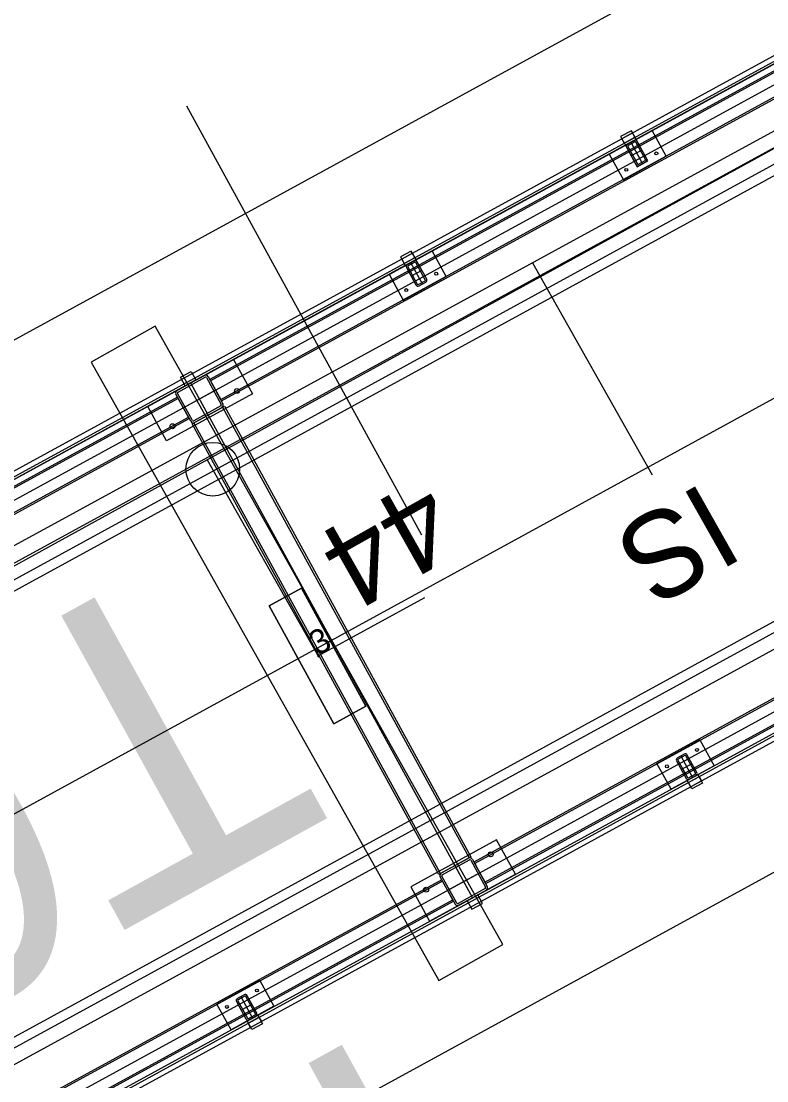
# Model space of a CAD drawing. Extents: x -783978 to -783565, y -1064821 to -1064596.
# Drawn here: x -783779.173 to -783776.126, y -1064690.963 to -1064686.63 of the extents above; entities that cross this region are included whole.
import ezdxf

# ---------------------------------------------------------------- set-up
doc = ezdxf.new("R2010")
doc.units = 0
for name, color, linetype in [('Default', 7, 'Continuous'), ('SO 01_20_01', 7, 'Continuous'), ('SO 01_50_01', 7, 'Continuous'), ('SO 01_74_01', 7, 'Continuous'), ('SO 01_77_01', 7, 'Continuous'), ('SO 01_86_04', 7, 'Continuous')]:
    doc.layers.add(name, color=color, linetype=linetype)

# ---------------------------------------------------------------- blocks, each defined once
blk = doc.blocks.new('POINT_DISPLAY')
at = {"layer": 'Default'}
blk.add_line((0, 0), (0, 0), dxfattribs=at)

msp = doc.modelspace()

# ---------------------------------------------------------------- linework, layer by layer
at = {"layer": 'SO 01_20_01'}
for p, q in [((-783735.0054, -1064663.7532), (-783787.4671, -1064692.4555)), ((-783735.2041, -1064664.4318), (-783786.7885, -1064692.6541)), ((-783786.6445, -1064692.9173), (-783735.3233, -1064664.839)), ((-783738.0171, -1064666.3812), (-783786.4402, -1064692.874)), ((-783786.421, -1064692.9091), (-783737.9979, -1064666.4163)), ((-783737.8741, -1064667.2605), (-783785.3352, -1064693.2269)), ((-783785.6531, -1064694.3127), (-783737.23, -1064667.82)), ((-783737.0912, -1064667.858), (-783785.7805, -1064694.4964)), ((-783737.2108, -1064667.855), (-783785.6339, -1064694.3478)), ((-783785.6366, -1064694.7596), (-783736.9472, -1064668.1212)), ((-783746.2961, -1064673.8055), (-783785.8354, -1064695.4379))]:
    msp.add_line(p, q, dxfattribs=at)
at = {"layer": 'SO 01_50_01'}
for p, q in [((-783786.7885, -1064692.6541), (-783725.4827, -1064659.1131)), ((-783778.0156, -1064687.8544), (-783773.6292, -1064685.4546)), ((-783778.0156, -1064687.8545), (-783773.6292, -1064685.4547)), ((-783778.0156, -1064687.8545), (-783773.6292, -1064685.4547)), ((-783777.5357, -1064688.7317), (-783778.4956, -1064686.9771)), ((-783782.4021, -1064690.2543), (-783778.0156, -1064687.8544)), ((-783782.402, -1064690.2544), (-783778.0156, -1064687.8545)), ((-783782.402, -1064690.2544), (-783778.0156, -1064687.8545))]:
    msp.add_line(p, q, dxfattribs=at)
at = {"layer": 'SO 01_74_01'}
for p, q in [((-783735.2185, -1064664.4055), (-783786.6099, -1064692.5222)), ((-783786.6003, -1064692.5398), (-783735.2089, -1064664.423)), ((-783785.4388, -1064694.6628), (-783745.8293, -1064672.9921)), ((-783745.8197, -1064673.0096), (-783785.4292, -1064694.6803)), ((-783775.8367, -1064686.6908), (-783778.4028, -1064688.0947)), ((-783775.8337, -1064686.6964), (-783778.3998, -1064688.1003)), ((-783778.3578, -1064688.1769), (-783775.7918, -1064686.773)), ((-783778.3548, -1064688.1825), (-783775.7888, -1064686.7786)), ((-783776.6794, -1064687.0778), (-783776.7233, -1064687.1018)), ((-783776.7233, -1064687.1018), (-783776.7041, -1064687.1369)), ((-783776.6746, -1064687.0866), (-783776.7185, -1064687.1106)), ((-783776.7185, -1064687.1106), (-783776.7089, -1064687.1281)), ((-783776.7089, -1064687.1281), (-783776.665, -1064687.1041)), ((-783776.7041, -1064687.1369), (-783776.6602, -1064687.1129)), ((-783776.6602, -1064687.1129), (-783776.6794, -1064687.0778)), ((-783776.665, -1064687.1041), (-783776.6746, -1064687.0866)), ((-783777.5787, -1064687.5698), (-783777.6225, -1064687.5938)), ((-783777.6225, -1064687.5938), (-783777.6033, -1064687.6288)), ((-783777.5739, -1064687.5785), (-783777.6177, -1064687.6025)), ((-783777.6081, -1064687.6201), (-783777.5643, -1064687.5961)), ((-783777.5595, -1064687.6048), (-783777.5787, -1064687.5698)), ((-783777.5643, -1064687.5961), (-783777.5739, -1064687.5785)), ((-783777.6177, -1064687.6025), (-783777.6081, -1064687.6201)), ((-783777.6033, -1064687.6288), (-783777.5595, -1064687.6048)), ((-783778.5217, -1064688.0857), (-783778.4779, -1064688.0617)), ((-783778.4779, -1064688.0617), (-783778.4587, -1064688.0968)), ((-783778.5025, -1064688.1208), (-783778.5217, -1064688.0857)), ((-783778.4587, -1064688.0968), (-783778.5025, -1064688.1208)), ((-783778.4028, -1064688.0947), (-783778.3548, -1064688.1825)), ((-783778.3998, -1064688.1003), (-783778.3578, -1064688.1769)), ((-783778.5344, -1064688.1667), (-783781.1005, -1064689.5707)), ((-783778.5314, -1064688.1723), (-783781.0974, -1064689.5762)), ((-783778.4864, -1064688.2545), (-783778.5344, -1064688.1667)), ((-783778.4894, -1064688.2489), (-783778.5314, -1064688.1723)), ((-783778.4744, -1064688.2764), (-783778.3428, -1064688.2044)), ((-783778.4674, -1064688.2726), (-783778.3498, -1064688.2082)), ((-783778.3498, -1064688.2082), (-783777.3419, -1064690.0505)), ((-783778.3428, -1064688.2044), (-783777.3349, -1064690.0467)), ((-783781.0555, -1064689.6529), (-783778.4894, -1064688.2489)), ((-783781.0525, -1064689.6584), (-783778.4864, -1064688.2545)), ((-783777.4665, -1064690.1187), (-783778.4744, -1064688.2764)), ((-783777.4594, -1064690.1149), (-783778.4674, -1064688.2726)), ((-783774.7568, -1064688.6647), (-783777.3229, -1064690.0686)), ((-783774.7538, -1064688.6703), (-783777.3198, -1064690.0742)), ((-783777.2779, -1064690.1508), (-783774.7118, -1064688.7469)), ((-783777.2749, -1064690.1564), (-783774.7088, -1064688.7525)), ((-783776.4514, -1064689.7343), (-783776.4075, -1064689.7103)), ((-783776.4466, -1064689.7431), (-783776.4027, -1064689.7191)), ((-783776.4075, -1064689.7103), (-783776.3883, -1064689.7454)), ((-783776.4027, -1064689.7191), (-783776.3931, -1064689.7366)), ((-783776.4322, -1064689.7694), (-783776.4514, -1064689.7343)), ((-783776.437, -1064689.7606), (-783776.4466, -1064689.7431)), ((-783776.3931, -1064689.7366), (-783776.437, -1064689.7606)), ((-783776.3883, -1064689.7454), (-783776.4322, -1064689.7694)), ((-783777.3349, -1064690.0467), (-783777.4665, -1064690.1187)), ((-783777.3419, -1064690.0505), (-783777.4594, -1064690.1149)), ((-783777.3229, -1064690.0686), (-783777.2749, -1064690.1564)), ((-783777.3198, -1064690.0742), (-783777.2779, -1064690.1508)), ((-783777.4545, -1064690.1406), (-783780.0205, -1064691.5445)), ((-783777.4514, -1064690.1462), (-783780.0175, -1064691.5501)), ((-783777.4065, -1064690.2284), (-783777.4545, -1064690.1406)), ((-783777.4095, -1064690.2228), (-783777.4514, -1064690.1462)), ((-783779.9755, -1064691.6267), (-783777.4095, -1064690.2228)), ((-783779.9725, -1064691.6323), (-783777.4065, -1064690.2284)), ((-783777.3067, -1064690.2023), (-783777.3506, -1064690.2263)), ((-783777.3506, -1064690.2263), (-783777.3314, -1064690.2614)), ((-783777.3314, -1064690.2614), (-783777.2875, -1064690.2374)), ((-783777.2875, -1064690.2374), (-783777.3067, -1064690.2023)), ((-783778.2498, -1064690.7183), (-783778.206, -1064690.6943)), ((-783778.245, -1064690.727), (-783778.2012, -1064690.703)), ((-783778.206, -1064690.6943), (-783778.1868, -1064690.7294)), ((-783778.2012, -1064690.703), (-783778.1916, -1064690.7206)), ((-783778.2306, -1064690.7534), (-783778.2498, -1064690.7183)), ((-783778.2354, -1064690.7446), (-783778.245, -1064690.727)), ((-783778.1916, -1064690.7206), (-783778.2354, -1064690.7446)), ((-783778.1868, -1064690.7294), (-783778.2306, -1064690.7534))]:
    msp.add_line(p, q, dxfattribs=at)
for points in [[(-783735.1681, -1064664.4976), (-783787.4762, -1064693.1159)], [(-783734.0882, -1064666.4715), (-783786.3963, -1064695.0898)], [(-783776.6685, -1064687.1174), (-783776.6958, -1064687.1323)], [(-783776.6996, -1064687.1452), (-783776.6606, -1064687.2163)], [(-783776.694, -1064687.1421), (-783776.6551, -1064687.2133)], [(-783776.6655, -1064687.1229), (-783776.6928, -1064687.1379)], [(-783776.6822, -1064687.1249), (-783776.6342, -1064687.2126)], [(-783776.6362, -1064687.1567), (-783776.6801, -1064687.1807)], [(-783776.6223, -1064687.1953), (-783776.6612, -1064687.1242)], [(-783776.6168, -1064687.1923), (-783776.6557, -1064687.1212)], [(-783776.6508, -1064687.2145), (-783776.6236, -1064687.1996)], [(-783776.6478, -1064687.2201), (-783776.6205, -1064687.2051)], [(-783777.5988, -1064687.6371), (-783777.5599, -1064687.7083)], [(-783777.5677, -1064687.6094), (-783777.595, -1064687.6243)], [(-783777.5933, -1064687.6341), (-783777.5543, -1064687.7053)], [(-783777.5647, -1064687.6149), (-783777.592, -1064687.6298)], [(-783777.5814, -1064687.6168), (-783777.5334, -1064687.7046)], [(-783777.5215, -1064687.6873), (-783777.5604, -1064687.6162)], [(-783777.516, -1064687.6843), (-783777.5549, -1064687.6131)], [(-783777.5355, -1064687.6487), (-783777.5793, -1064687.6727)], [(-783777.5501, -1064687.7065), (-783777.5228, -1064687.6916)], [(-783777.547, -1064687.712), (-783777.5197, -1064687.6971)], [(-783778.5359, -1064688.1391), (-783778.4253, -1064688.0786)], [(-783778.532, -1064688.1461), (-783778.4215, -1064688.0856)], [(-783778.4806, -1064688.1088), (-783777.3287, -1064690.2143)], [(-783778.4806, -1064688.1088), (-783778.4086, -1064688.2404)], [(-783778.4161, -1064688.0872), (-783778.3556, -1064688.1977)], [(-783778.409, -1064688.0833), (-783778.3486, -1064688.1939)], [(-783778.4802, -1064688.2659), (-783778.5406, -1064688.1553)], [(-783778.4731, -1064688.262), (-783778.5336, -1064688.1515)], [(-783778.3788, -1064688.1386), (-783778.5104, -1064688.2106)], [(-783778.3572, -1064688.2031), (-783778.4677, -1064688.2636)], [(-783778.3533, -1064688.2102), (-783778.4639, -1064688.2706)], [(-783776.4638, -1064689.6271), (-783776.4911, -1064689.6421)], [(-783776.4608, -1064689.6327), (-783776.4881, -1064689.6476)], [(-783776.4121, -1064689.702), (-783776.451, -1064689.6309)], [(-783776.4949, -1064689.6549), (-783776.4559, -1064689.726)], [(-783776.4893, -1064689.6519), (-783776.4504, -1064689.723)], [(-783776.4775, -1064689.6346), (-783776.4295, -1064689.7223)], [(-783776.4315, -1064689.6665), (-783776.4754, -1064689.6905)], [(-783776.4176, -1064689.7051), (-783776.4565, -1064689.6339)], [(-783776.4461, -1064689.7243), (-783776.4188, -1064689.7093)], [(-783776.4431, -1064689.7298), (-783776.4158, -1064689.7149)], [(-783777.4559, -1064690.1129), (-783777.3454, -1064690.0525)], [(-783777.4521, -1064690.12), (-783777.3416, -1064690.0595)], [(-783777.3361, -1064690.0611), (-783777.2757, -1064690.1716)], [(-783777.3291, -1064690.0572), (-783777.2686, -1064690.1678)], [(-783777.4007, -1064690.0827), (-783777.3287, -1064690.2143)], [(-783777.4002, -1064690.2398), (-783777.4607, -1064690.1292)], [(-783777.3932, -1064690.2359), (-783777.4537, -1064690.1254)], [(-783777.2989, -1064690.1125), (-783777.4305, -1064690.1845)], [(-783777.2772, -1064690.177), (-783777.3878, -1064690.2375)], [(-783777.2734, -1064690.1841), (-783777.3839, -1064690.2445)], [(-783778.2622, -1064690.6111), (-783778.2895, -1064690.626)], [(-783778.2592, -1064690.6166), (-783778.2865, -1064690.6315)], [(-783778.2759, -1064690.6185), (-783778.2279, -1064690.7063)], [(-783778.216, -1064690.689), (-783778.2549, -1064690.6179)], [(-783778.2105, -1064690.686), (-783778.2494, -1064690.6148)], [(-783778.2933, -1064690.6388), (-783778.2544, -1064690.71)], [(-783778.2878, -1064690.6358), (-783778.2488, -1064690.707)], [(-783778.23, -1064690.6504), (-783778.2738, -1064690.6744)], [(-783778.2446, -1064690.7082), (-783778.2173, -1064690.6933)], [(-783778.2415, -1064690.7137), (-783778.2142, -1064690.6988)]]:
    msp.add_lwpolyline(points, dxfattribs=at)
for points in [[(-783776.5944, -1064687.0769), (-783776.7699, -1064687.1729), (-783776.7123, -1064687.2781), (-783776.5368, -1064687.1822)], [(-783776.6602, -1064687.1129), (-783776.7041, -1064687.1369), (-783776.6561, -1064687.2246), (-783776.6122, -1064687.2006)], [(-783777.4937, -1064687.5688), (-783777.6691, -1064687.6648), (-783777.6115, -1064687.7701), (-783777.4361, -1064687.6741)], [(-783778.2284, -1064688.1532), (-783778.5793, -1064688.3452), (-783778.6561, -1064688.2048), (-783778.3051, -1064688.0128)], [(-783776.3417, -1064689.6743), (-783776.5172, -1064689.7703), (-783776.5748, -1064689.665), (-783776.3993, -1064689.5691)], [(-783777.23, -1064689.9779), (-783777.5809, -1064690.1699), (-783777.5041, -1064690.3103), (-783777.1532, -1064690.1183)], [(-783778.1402, -1064690.6583), (-783778.3156, -1064690.7543), (-783778.3732, -1064690.649), (-783778.1978, -1064690.553)]]:
    msp.add_lwpolyline(points, close=True, dxfattribs=at)
for centre, radius in [((-783776.5776, -1064687.1702), 0.006), ((-783776.7004, -1064687.2374), 0.006), ((-783777.4768, -1064687.6622), 0.006), ((-783777.5996, -1064687.7294), 0.006), ((-783778.2914, -1064688.1421), 0.01), ((-783778.5546, -1064688.2861), 0.01), ((-783776.4112, -1064689.6098), 0.006), ((-783776.5341, -1064689.677), 0.006), ((-783777.2547, -1064690.037), 0.01), ((-783777.5179, -1064690.181), 0.01), ((-783778.2097, -1064690.5937), 0.006), ((-783778.3325, -1064690.6609), 0.006)]:
    msp.add_circle(centre, radius, dxfattribs=at)
for centre, radius, start, end in [((-783776.664, -1064687.1257), 0.00945, 28.6835, 118.6835), ((-783776.6913, -1064687.1406), 0.00945, 118.6835, 208.6835), ((-783776.6913, -1064687.1406), 0.00315, 118.6835, 208.6835), ((-783776.664, -1064687.1257), 0.00315, 28.6835, 118.6835), ((-783776.6251, -1064687.1968), 0.00315, 298.6835, 28.6835), ((-783776.6251, -1064687.1968), 0.00945, 298.6835, 28.6835), ((-783776.6524, -1064687.2118), 0.00945, 208.6835, 298.6835), ((-783776.6524, -1064687.2118), 0.00315, 208.6835, 298.6835), ((-783777.5905, -1064687.6326), 0.00945, 118.6835, 208.6835), ((-783777.5905, -1064687.6326), 0.00315, 118.6835, 208.6835), ((-783777.5632, -1064687.6177), 0.00945, 28.6835, 118.6835), ((-783777.5632, -1064687.6177), 0.00315, 28.6835, 118.6835), ((-783777.5516, -1064687.7037), 0.00945, 208.6835, 298.6835), ((-783777.5516, -1064687.7037), 0.00315, 208.6835, 298.6835), ((-783777.5243, -1064687.6888), 0.00315, 298.6835, 28.6835), ((-783777.5243, -1064687.6888), 0.00945, 298.6835, 28.6835), ((-783778.4196, -1064688.0891), 0.012, 28.6835, 118.6835), ((-783778.4196, -1064688.0891), 0.004, 28.6835, 118.6835), ((-783778.5301, -1064688.1496), 0.012, 118.6835, 208.6835), ((-783778.5301, -1064688.1496), 0.004, 118.6835, 208.6835), ((-783778.3591, -1064688.1996), 0.004, 298.6835, 28.6835), ((-783778.3591, -1064688.1996), 0.012, 298.6835, 28.6835), ((-783778.4696, -1064688.2601), 0.012, 208.6835, 298.6835), ((-783778.4696, -1064688.2601), 0.004, 208.6835, 298.6835), ((-783776.4593, -1064689.6354), 0.00945, 28.6835, 118.6835), ((-783776.4593, -1064689.6354), 0.00315, 28.6835, 118.6835), ((-783776.4866, -1064689.6504), 0.00945, 118.6835, 208.6835), ((-783776.4866, -1064689.6504), 0.00315, 118.6835, 208.6835), ((-783776.4204, -1064689.7066), 0.00315, 298.6835, 28.6835), ((-783776.4204, -1064689.7066), 0.00945, 298.6835, 28.6835), ((-783776.4476, -1064689.7215), 0.00945, 208.6835, 298.6835), ((-783776.4476, -1064689.7215), 0.00315, 208.6835, 298.6835), ((-783777.3396, -1064690.063), 0.012, 28.6835, 118.6835), ((-783777.3396, -1064690.063), 0.004, 28.6835, 118.6835), ((-783777.4502, -1064690.1235), 0.012, 118.6835, 208.6835), ((-783777.4502, -1064690.1235), 0.004, 118.6835, 208.6835), ((-783777.2792, -1064690.1735), 0.004, 298.6835, 28.6835), ((-783777.2792, -1064690.1735), 0.012, 298.6835, 28.6835), ((-783777.3897, -1064690.234), 0.012, 208.6835, 298.6835), ((-783777.3897, -1064690.234), 0.004, 208.6835, 298.6835), ((-783778.285, -1064690.6343), 0.00945, 118.6835, 208.6835), ((-783778.2577, -1064690.6194), 0.00945, 28.6835, 118.6835), ((-783778.2577, -1064690.6194), 0.00315, 28.6835, 118.6835), ((-783778.285, -1064690.6343), 0.00315, 118.6835, 208.6835), ((-783778.2461, -1064690.7054), 0.00945, 208.6835, 298.6835), ((-783778.2461, -1064690.7054), 0.00315, 208.6835, 298.6835), ((-783778.2188, -1064690.6905), 0.00315, 298.6835, 28.6835), ((-783778.2188, -1064690.6905), 0.00945, 298.6835, 28.6835)]:
    msp.add_arc(centre, radius, start, end, dxfattribs=at)
at = {"layer": 'SO 01_77_01'}
msp.add_lwpolyline([(-783777.2054, -1064690.4059), (-783778.6255, -1064687.8774), (-783778.8871, -1064688.0244), (-783777.4669, -1064690.5528)], close=True, dxfattribs=at)
at = {"layer": 'SO 01_86_04'}
for p, q in [((-783777.0841, -1064687.6174), (-783776.594, -1064688.485)), ((-783778.4125, -1064688.4232), (-783777.9565, -1064689.2305)), ((-783778.028, -1064688.9489), (-783778.1595, -1064689.0209)), ((-783778.028, -1064688.9489), (-783778.1595, -1064689.0209)), ((-783778.1595, -1064689.0209), (-783778.028, -1064688.9489)), ((-783778.1595, -1064689.0209), (-783778.028, -1064688.9489)), ((-783777.764, -1064689.4314), (-783778.028, -1064688.9489)), ((-783777.764, -1064689.4314), (-783778.028, -1064688.9489)), ((-783778.028, -1064688.9489), (-783777.764, -1064689.4314)), ((-783778.028, -1064688.9489), (-783777.764, -1064689.4314)), ((-783778.1595, -1064689.0209), (-783777.8956, -1064689.5034)), ((-783778.1595, -1064689.0209), (-783777.8956, -1064689.5034)), ((-783777.8956, -1064689.5034), (-783778.1595, -1064689.0209)), ((-783777.8956, -1064689.5034), (-783778.1595, -1064689.0209)), ((-783777.9618, -1064689.2262), (-783777.5231, -1064688.9862)), ((-783777.8956, -1064689.5034), (-783777.764, -1064689.4314)), ((-783777.8956, -1064689.5034), (-783777.764, -1064689.4314)), ((-783777.764, -1064689.4314), (-783777.8956, -1064689.5034)), ((-783777.764, -1064689.4314), (-783777.8956, -1064689.5034))]:
    msp.add_line(p, q, dxfattribs=at)
for points in [[(-783738.3222, -1064666.4797), (-783740.5325, -1064667.689), (-783743.1715, -1064669.1328), (-783745.7538, -1064670.5456), (-783748.4385, -1064672.0145), (-783751.0413, -1064673.4385), (-783753.6847, -1064674.8847), (-783756.3281, -1064676.3309), (-783758.9715, -1064677.7772), (-783761.6149, -1064679.2234), (-783764.2583, -1064680.6696), (-783766.9018, -1064682.1159), (-783769.4633, -1064683.5173), (-783772.109, -1064684.9648), (-783774.7882, -1064686.4306), (-783778.1382, -1064688.2722), (-783783.8139, -1064691.3971), (-783785.747, -1064692.4898)], [(-783747.063, -1064670.9765), (-783746.9575, -1064671.1681), (-783786.6893, -1064692.8619), (-783786.185, -1064693.7636)]]:
    msp.add_lwpolyline(points, dxfattribs=at)
msp.add_circle((-783778.39, -1064688.4618), 0.1097, dxfattribs=at)

# ---------------------------------------------------------------- block references
at = {"layer": 'SO 01_86_04', "xscale": 0.010000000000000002, "yscale": 0.009999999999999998, "rotation": 28.683491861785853}
for p in [(-783778.028, -1064688.9489), (-783778.028, -1064688.9489), (-783778.1595, -1064689.0209), (-783778.1595, -1064689.0209), (-783777.764, -1064689.4314), (-783777.764, -1064689.4314), (-783777.8956, -1064689.5034), (-783777.8956, -1064689.5034)]:
    msp.add_blockref('POINT_DISPLAY', p, dxfattribs=at)

# ---------------------------------------------------------------- texts
at = {"layer": 'SO 01_77_01'}
for s, p in [('T6', (-783778.4945, -1064688.7767)), ('T2', (-783777.484, -1064690.6064))]:
    msp.add_text(s, height=1.25, rotation=208.9107, dxfattribs=at).set_placement(p)
at = {"layer": 'SO 01_86_04'}
for s, height, rotation, p in [('IS', 0.351, 209.46, (-783776.3815, -1064688.5109)), ('44', 0.351, 209.46, (-783777.5284, -1064688.4867)), ('3', 0.1, 28.6835, (-783777.9618, -1064689.2262))]:
    msp.add_text(s, height=height, rotation=rotation, dxfattribs=at).set_placement(p)

doc.saveas('drawing.dxf')
